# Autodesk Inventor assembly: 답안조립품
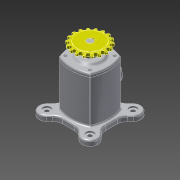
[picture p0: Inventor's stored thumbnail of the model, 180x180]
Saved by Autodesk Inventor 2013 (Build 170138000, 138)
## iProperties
Created: 2016-05
Part Number: 답안조립품
Document SubType Name: Assembly
Designer: Administrator
Author: Administrator
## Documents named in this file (11)
- C:\Users\Administrator\Desktop\460508V1012\답안조립품.iam
- C:\Users\Administrator\Desktop\460508V1012\본체.ipt
- C:\Users\Administrator\Desktop\460508V1012\편심축.ipt
- C:\Users\Administrator\Desktop\460508V1012\키5x5.ipt
- C:\Users\Administrator\Desktop\460508V1012\스프로킷.ipt
- C:\Users\Administrator\Desktop\460508V1012\오일실.ipt
- C:\Users\Administrator\Desktop\460508V1012\커버.ipt
- C:\Users\Administrator\Desktop\460508V1012\베어링-6203.ipt
- C:\Users\Administrator\Desktop\460508V1012\M4x0.7x12.ipt
- C:\Users\Administrator\Desktop\460508V1012\슬라이더.ipt
- C:\Users\Administrator\Desktop\460508V1012\부시.ipt
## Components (8 placed, 1 different names)
1. M4x0.7x12:1
2. M4x0.7x12:3
3. M4x0.7x12:4
4. M4x0.7x12:5
5. M4x0.7x12:2
6. M4x0.7x12:6
7. M4x0.7x12:7
8. M4x0.7x12:8
